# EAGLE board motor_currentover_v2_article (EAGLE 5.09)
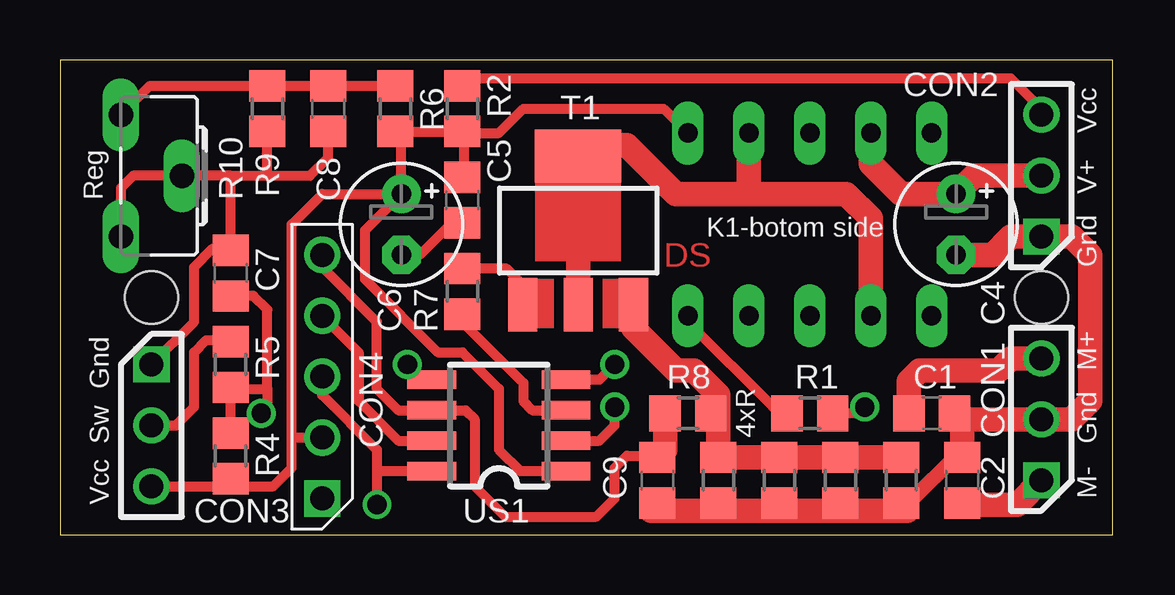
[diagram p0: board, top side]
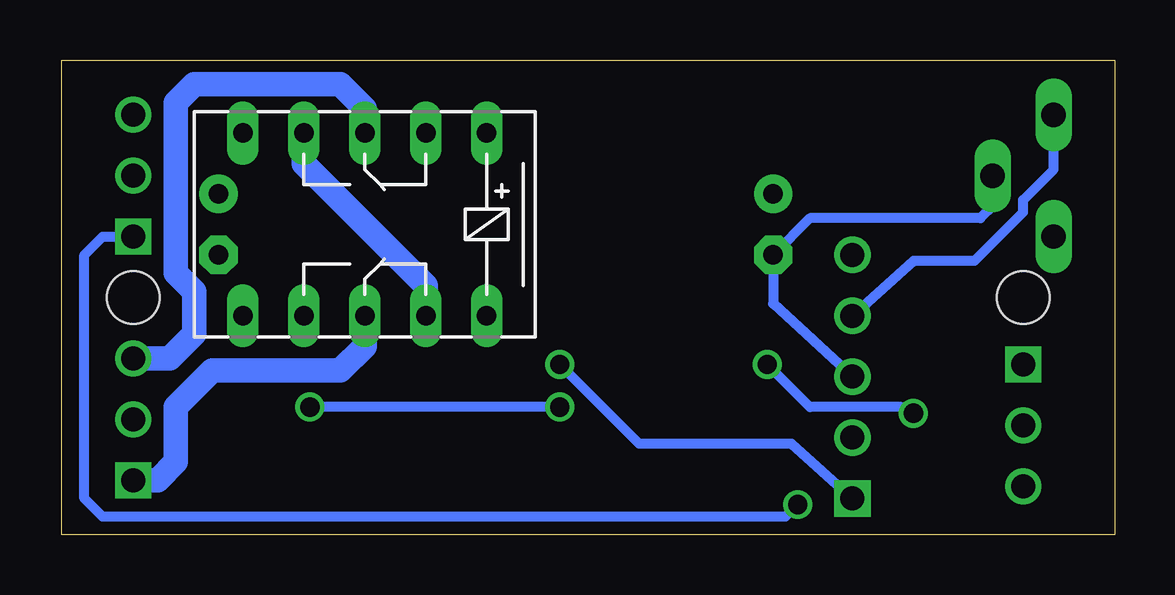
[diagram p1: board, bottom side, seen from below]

Size 43.87 x 19.8 mm. Coordinates in mm from the lower left corner, seen from the top.
Outline: 0,0 43.87,0 43.87,19.8 0,19.8 0,0
Copper layers (1*16): Top 0.035mm / dielectric 1.5mm / Bottom 0.035mm
Design rules "default": minimum track width 10mil, minimum drill 24mil, track to track 8mil, track to pad 8mil, pad to pad 8mil, via to via 8mil, smd to smd 8mil, copper to edge 40mil, drill to drill 8mil, minimum pad ring 10mil, minimum via ring 8mil, stop-mask expansion 4mil, vias tented up to drill 0mil, thermal gap 10mil
Holes 2.2 mm at 3.81,9.91 40.89,9.91

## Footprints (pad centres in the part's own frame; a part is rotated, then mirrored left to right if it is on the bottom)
C0805 = smd 1.3 x 1.5: 1 -0.95,0; 2 0.95,0
E2,5-5 = drill 0.813 pad 1.6 round: + -1.27,0 | drill 0.813 pad 1.6 octagon: - 1.27,0
GOLDPIN_1X3 = drill 1 square: P$1 -2.54,0 | drill 1 round: P$2 0,0; P$3 2.54,0
ICSP = drill 1 square: 1 -5.08,0 | drill 1 round: 2 -2.54,0; 3 0,0; 4 2.54,0; 5 5.08,0
G6H2-100 = drill 0.813 long: 1 -5.08,-3.81; 5 5.08,-3.81; 6 5.08,3.81; 10 -5.08,3.81; O1 -2.54,-3.81; O2 -2.54,3.81; P1 0,-3.81; P2 0,3.81; S1 2.54,-3.81; S2 2.54,3.81
R0805 = smd 1.3 x 1.5: 1 -0.95,0; 2 0.95,0
CA6H = drill 1.016 long: A -2.54,0; E 2.54,0; S 0,2.54
SOT223 = smd 1.219 x 2.235: 1 -2.311,-3.099; 2 0,-3.099; 3 2.311,-3.099 | smd 3.6 x 2.2: 4 0,3.099
SO8 = smd 0.762 x 2.032: 1 -1.905,-2.794; 2 -0.635,-2.794; 3 0.635,-2.794; 4 1.905,-2.794; 5 1.905,2.794; 6 0.635,2.794; 7 -0.635,2.794; 8 -1.905,2.794

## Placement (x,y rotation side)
C1  100n  [C0805]  36.32,5.08 0 top
C2  100n  [C0805]  37.59,2.29 90 top
C4  100uF  [E2,5-5]  37.34,12.95 270 top
C5  100n  [C0805]  16.76,13.97 270 top
C6  100uF  [E2,5-5]  14.22,12.95 270 top
C7  100n  [C0805]  7.11,10.92 90 top
C8  100n  [C0805]  11.18,17.78 270 top
C9  100n  [C0805]  24.89,2.29 270 top
CON1  MTR  [GOLDPIN_1X3]  40.89,4.83 90 top
CON2  POW  [GOLDPIN_1X3]  40.89,14.99 90 top
CON3  SW  [GOLDPIN_1X3]  3.81,4.57 270 top
CON4  PROG  [ICSP]  10.92,6.6 90 top
K1  AZ850  [G6H2-100]  31.24,12.95 180 bottom
R1  10R  [R0805]  31.24,5.08 0 top
R2  10R  [R0805]  16.76,17.78 90 top
R4  1k  [R0805]  7.11,3.3 270 top
R5  10R  [R0805]  7.11,7.11 90 top
R6  10k  [R0805]  13.97,17.78 270 top
R7  1k  [R0805]  16.76,10.16 270 top
R8  1k  [R0805]  26.16,5.08 180 top
R9  *  [R0805]  8.64,17.78 90 top
R10  20k  [CA6H]  2.54,14.99 270 top
R11  10R  [R0805]  35.05,2.29 90 top
R12  10R  [R0805]  32.51,2.29 90 top
R13  10R  [R0805]  29.97,2.29 90 top
R14  10R  [R0805]  27.43,2.29 90 top
T1  [SOT223]  21.59,12.7 0 top
US1  PIC12F675  [SO8]  18.29,4.57 90 top

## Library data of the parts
C1 C2 C4-C9 R1 R2 R4-R9 R11-R14 = rcl
CON1-CON3 = DS
CON4 US1 = DS_microchip
K1 = relay
R10 = pot
T1 = transistor-power

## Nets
CURR: C9.1 CON4.5 R8.2 US1.6
DIR: R1.2 US1.2
GND: C1.2 C2.2 C4.- C5.2 C6.- C7.2 C8.2 C9.2 CON1.P$2 CON2.P$1 CON3.P$1 CON4.3 R9.1 R10.E R10.S R11.1 R12.1 R13.1 R14.1 US1.8
MTR_N: C2.1 CON1.P$1 K1.P2
MTR_P: C1.1 CON1.P$3 K1.P1
N$1: R8.1 R11.2 R12.2 R13.2 R14.2 T1.3
N$4: R7.1 T1.1
N$5: CON2.P$3 R2.2
N$6: K1.O1 K1.S2 T1.2
N$7: CON3.P$2 R5.2
N$8: K1.10 R1.1
P_ON: R7.2 US1.3
RST: CON4.1 US1.4
SETT: C8.1 CON4.4 R6.1 R9.2 R10.A US1.7
SW: C7.1 R4.1 R5.1 US1.5
V+: C4.+ CON2.P$2 K1.O2 K1.S1
VCC: C5.1 C6.+ CON3.P$3 CON4.2 K1.1 R2.1 R4.2 R6.2 US1.1

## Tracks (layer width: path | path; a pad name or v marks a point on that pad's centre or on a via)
CURR
  Top 0.406: 24.83,3.3 23.62,3.3 23.11,2.79 23.11,1.52 22.35,0.76 18.54,0.76 17.27,2.03 17.27,4.83 16.89,5.21 US1.6 14.1,5.21 13.21,6.1 13.21,8.89 10.92,11.18 CON4.5
  Top 0.61: 24.83,3.3 C9.1
  Top 1.016: R8.2 25.21,3.56 C9.1
DIR  (via drill 0.8)
  Top 0.406: v33.53,5.33 33.27,5.08 R1.2 | US1.2 22.48,3.94 23.11,4.57 v23.11,5.33
  Bottom 0.406: v23.11,5.33 v33.53,5.33
GND  (via drill 0.8)
  Top 0.406: CON4.3 10.92,5.84 13.21,3.56 13.21,2.54 | 13.21,2.54 v13.21,1.27 | US1.8 13.34,2.67 13.21,2.54 | C8.2 11.18,15.75 10.41,14.99 8.64,14.99 | 7.11,14.99 R10.S 3.05,14.99 2.54,14.48 R10.E | 7.11,14.99 8.64,14.99 | 8.64,14.99 R9.1 | 7.11,14.99 C7.2 7.05,11.94 6.35,11.94 5.59,11.18 5.59,8.89 CON3.P$1 | C5.2 16.32,13.02 14.99,11.68 C6.-
  Top 0.61: 37.27,3.24 35.56,1.52 35.24,1.52
  Top 0.813: C2.2 37.27,3.24 | 35.24,1.52 R11.1
  Top 1.016: C4.- 38.86,11.68 39.62,12.45 CON2.P$1 42.16,12.45 42.93,11.68 42.93,5.59 42.16,4.83 CON1.P$2 37.78,4.83 | 37.78,4.83 C1.2 | C2.2 37.59,4.64 37.78,4.83 | C9.2 24.64,1.02 27.18,1.02 | 29.97,1.02 27.18,1.02 | 29.97,1.02 32.51,1.02 R12.1 32.58,1.02 35.31,1.02 R11.1 | 29.97,1.02 R13.1 | 27.18,1.02 R14.1
  Bottom 0.406: CON2.P$1 42.16,12.45 42.93,11.68 42.93,1.52 42.16,0.76 13.72,0.76 v13.21,1.27 | CON4.3 14.22,9.65 C6.- 12.7,13.21 5.59,13.21 5.08,13.72 R10.S
MTR_N
  Top 0.813: C2.1 37.66,1.27
  Top 1.016: CON1.P$1 39.88,1.27 37.66,1.27
  Bottom 1.016: K1.P2 31.24,7.87 32.26,6.86 37.59,6.86 39.12,5.33 39.12,3.05 39.88,2.29 CON1.P$1
MTR_P
  Top 1.016: C1.1 35.37,6.42 35.81,6.86 39.12,6.86 39.62,7.37 CON1.P$3
  Bottom 1.016: K1.P1 31.24,17.78 32.26,18.8 38.35,18.8 39.12,18.03 39.12,10.92 38.35,10.16 38.35,8.38 39.37,7.37 CON1.P$3
N$1
  Top 0.61: R8.1 27.43,5.33
  Top 1.016: R11.2 R12.2 R13.2 R14.2 27.43,5.65 | T1.3 23.88,9.58 23.88,8.64 25.65,6.86 26.42,6.86 27.43,5.84 27.43,5.65 | 27.43,5.65 R8.1
N$4
  Top 0.406: R7.1 18.61,11.11 19.3,10.41 19.3,9.63 T1.1
N$5
  Top 0.406: CON2.P$3 40.89,17.78 39.62,19.05 17.08,19.05 R2.2
N$6
  Top 1.016: 28.7,14.22 25.65,14.22 23.62,16.26 21.59,16.26 T1.2 | 28.7,14.22 32.77,14.22 33.78,13.21 K1.S2 | 28.7,14.22 K1.O1
N$7
  Top 0.406: CON3.P$2 4.83,4.57 5.59,5.33 5.59,7.62 6.1,8.13 7.05,8.13 R5.2
N$8
  Top 0.406: K1.10 26.16,8.89 29.72,5.33 R1.1
P_ON
  Top 0.406: R7.2 16.76,8.89 19.3,6.35 19.3,5.59 19.68,5.21 US1.3
RST  (via drill 0.8)
  Top 0.406: US1.4 22.48,6.48 v23.11,7.11
  Bottom 0.406: v23.11,7.11 19.81,3.81 13.46,3.81 CON4.1
SETT
  Top 0.406: R6.1 C8.1 R9.2 3.74,18.73 R10.A | US1.7 14.1,3.94 12.45,5.59 12.45,7.62 CON4.4
  Bottom 0.406: CON4.4 8.38,11.43 5.84,11.43 3.81,13.46 3.81,13.97 2.54,15.24 R10.A
SW  (via drill 0.8)
  Top 0.406: R4.1 R5.1 7.18,6.1 8.64,6.1 | C7.1 8.06,9.97 8.64,9.4 8.64,6.1 | v14.48,7.11 15.24,6.35 15.37,6.35 US1.5 | 8.64,6.1 8.64,5.33 v8.38,5.08
  Bottom 0.406: v8.38,5.08 8.89,5.33 12.7,5.33 v14.48,7.11
V+
  Top 1.016: CON2.P$2 38.1,14.99 C4.+ 35.05,14.22 33.78,15.49 K1.S1
  Bottom 1.016: K1.O2 28.7,10.41 33.78,15.49 K1.S1
VCC
  Top 0.406: K1.1 25.15,17.78 19.3,17.78 18.29,16.76 16.83,16.76 | US1.1 19.18,2.67 18.29,3.56 18.29,6.1 16.76,7.62 15.75,7.62 12.7,10.67 12.7,12.7 C6.+ | 16.83,16.76 R2.1 R6.2 14.22,16.76 C6.+ | 16.83,16.76 16.83,14.99 C5.1 | 9.65,4.06 CON4.2 | 9.65,4.06 9.65,12.95 10.92,14.22 C6.+ | CON3.P$3 6.79,2.03 R4.2 7.43,2.03 8.89,2.03 9.65,2.79 9.65,4.06
(copper drawn outside any net)
  shapes: Top area x3

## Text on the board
Top: DS
tPlace: Vcc | Reg | V+ | K1-botom side | Gnd | M+ | Gnd | Sw | 4xR | Gnd | Vcc | M-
